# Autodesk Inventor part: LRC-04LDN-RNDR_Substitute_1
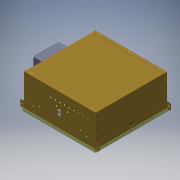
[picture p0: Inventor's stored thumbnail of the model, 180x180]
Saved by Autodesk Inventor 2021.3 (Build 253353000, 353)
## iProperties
Part Number: LRC-04LDN-RNDR_Substitute_1
Material: Generic
Document SubType Name: Modeling
Designer: JChurch
Manufacturer: Standard
Standards Organization: Custom
Density: 1 g/cm^3
Appearance: Smooth - Black
Author: JChurch
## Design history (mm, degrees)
derived "LRC-04LDN-RNDR.iam"
body "Solid9"
node "830520-00-00.ipt:1"
node "881088-00-00.iam:1::830140-00-00.ipt:1"
body "Solid10"
node "881088-00-00.iam:1::850014-00-00.iam:1::805044-00-00.ipt:1"
body "Solid11"
node "881088-00-00.iam:1::850014-00-00.iam:1::805174-00-00.ipt:1"
body "Solid12"
node "881088-00-00.iam:1::850014-00-00.iam:1::502055-00-00.ipt:1"
body "Solid13"
node "881088-00-00.iam:1::850014-00-00.iam:1::502055-00-00.ipt:2"
body "Solid14"
node "881088-00-00.iam:1::850014-00-00.iam:1::507032-00-00.ipt:1"
body "Solid15"
node "881088-00-00.iam:1::507000-00-00.ipt:1"
body "Solid16"
node "881088-00-00.iam:1::507000-00-00.ipt:2"
body "Solid17"
node "881088-00-00.iam:1::506002-00-00.ipt:1"
body "Solid18"
node "881088-00-00.iam:1::506002-00-00.ipt:2"
body "Solid19"
node "881088-00-00.iam:1::506002-00-00.ipt:3"
body "Solid20"
node "881088-00-00.iam:1::506002-00-00.ipt:4"
body "Solid21"
node "881088-00-00.iam:1::506002-00-00.ipt:5"
body "Solid22"
node "881088-00-00.iam:1::506002-00-00.ipt:6"
body "Solid23"
node "881088-00-00.iam:1::506002-00-00.ipt:7"
body "Solid24"
node "881088-00-00.iam:1::506002-00-00.ipt:8"
body "Solid25"
node "881088-00-00.iam:1::506002-00-00.ipt:9"
body "Solid26"
node "881088-00-00.iam:1::506002-00-00.ipt:10"
body "Solid27"
node "881088-00-00.iam:1::506002-00-00.ipt:11"
body "Solid28"
node "881088-00-00.iam:1::506002-00-00.ipt:12"
body "Solid29"
node "881088-00-00.iam:1::506002-00-00.ipt:13"
body "Solid30"
node "881088-00-00.iam:1::506002-00-00.ipt:14"
body "Solid31"
node "881088-00-00.iam:1::830392-01-00.iam:1::830392-00-00.ipt:1"
body "Solid32"
node "881088-00-00.iam:1::830392-01-00.iam:1::500027-00-00.ipt:1"
body "Solid33"
node "881088-00-00.iam:1::830392-01-00.iam:1::501030-00-00.ipt:1"
body "Solid34"
node "881088-00-00.iam:1::830392-01-00.iam:1::500027-00-00.ipt:2"
body "Solid35"
node "881088-00-00.iam:1::830392-01-00.iam:1::501030-00-00.ipt:2"
body "Solid36"
node "881088-00-00.iam:1::830392-01-00.iam:1::501030-00-00.ipt:3"
body "Solid37"
node "881088-00-00.iam:1::830392-01-00.iam:1::501030-00-00.ipt:4"
body "Solid38"
node "881088-00-00.iam:1::830392-01-00.iam:2::830392-00-00.ipt:1"
body "Solid39"
node "881088-00-00.iam:1::830392-01-00.iam:2::500027-00-00.ipt:1"
body "Solid40"
node "881088-00-00.iam:1::830392-01-00.iam:2::501030-00-00.ipt:1"
body "Solid41"
node "881088-00-00.iam:1::830392-01-00.iam:2::500027-00-00.ipt:2"
body "Solid42"
node "881088-00-00.iam:1::830392-01-00.iam:2::501030-00-00.ipt:2"
body "Solid43"
node "881088-00-00.iam:1::830392-01-00.iam:2::501030-00-00.ipt:3"
body "Solid44"
node "881088-00-00.iam:1::830392-01-00.iam:2::501030-00-00.ipt:4"
body "Solid45"
node "750031-00-XX.iam:1::710017-00-XX.ipt:1"
body "Solid46"
node "750031-00-XX.iam:1::710155-00-00.ipt:1"
body "Solid47"
node "750031-00-XX.iam:1::507035-01-38.ipt:1"
body "Solid48"
node "750031-00-XX.iam:1::507014-00-00.ipt:1"
body "Solid49"
node "750031-00-XX.iam:1::510048-00-00_4.16_DIA_NEW.ipt:1"
body "Solid50"
node "750031-00-XX.iam:1::507014-00-00.ipt:2"
body "Solid51"
node "750031-00-XX.iam:1::507035-01-38.ipt:2"
body "Solid52"
node "725377-00-00.ipt:1"
body "Solid53"
other parameters: "d15" = 61.595, "d16" = 9.525, "d17" = 9.525, "d35" = 5.08
